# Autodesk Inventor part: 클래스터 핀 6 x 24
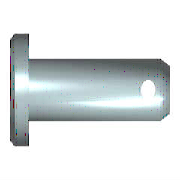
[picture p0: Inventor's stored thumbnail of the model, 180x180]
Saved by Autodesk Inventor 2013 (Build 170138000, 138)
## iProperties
IsCustomPart: 1
Created: 2012-02
Part Number: 클래스터 핀 6 x 24
Material: 강철
Description: 머리가 있는 클레비스 핀
Document SubType Name: Modeling
Standard: ISO 2341
Designer: mduedu
Standard Revision: Second edition 1986-11-01
Standards Organization: ISO
Language: ko-KR
Size Designation: B - 6 x 24
Categories: <MemberInstance><Categories><Category DisplayName="조임쇠" InternalName="e4da775c-781d-43d5-af7c-5136215cf5a6" Mnemonic="FSTN"><Category DisplayName="핀" InternalNa
Density: 7.85 g/cm^3
Author: mduedu
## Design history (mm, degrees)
sketch "스케치1"
  geometry: L1 (-2, 0)-(-2, 5); L2 (-2, 5)-(0, 5); L3 (0, 5)-(0, 3); L4 (0, 3)-(24, 3); L5 (24, 3)-(24, 0); L6 (-2, 0)-(24, 0); L7 (-4, 0)-(17, 0) reference; L8 (0, -0.98)-(0, 3.08) reference; C1 r 0.8 at (20.8, 0)
  constraints: 12 end point, 3 parallel, 2 collinear, 2 perpendicular, 1 centre point, 1 point on line, 1 vertical
  dimensions: "d0" = 6 diameter of L4 L6 (= NND); "d1" = 10 diameter of L2 L6 (= KOD); "d2" = 2 distance of L1.end L2.end (= KOH); "d3" = 24 distance of L3.end L4.end (= NLG); "d5" = 3.2 distance from line of L5 C1.centre (= DIST); "d6" = 1.6 diameter of C1 (= BOR)
revolve "본체" stored, may be unused: angle "d4" = 90 deg
extrude "구멍" cut sketch "스케치1" stored distance "d7" = 6 (= NND); taper "d8" = 0 deg
workaxis "Work Axis1"
workplane "Work Plane1"
node "작업축3"
node "작업 평면4"
body "Solid1"
chamfer "모따기1" distance "d9" = 1 (= PHH2); stored, may be unused: angle "d10" = 45 deg (= FAWI2), second distance "d16" = 1 (= PHH2)
chamfer "모따기2" distance "d11" = 2 (= PHH1); stored, may be unused: angle "d12" = 30 deg (= FAWI1), second distance "d17" = 2 (= PHH1)
other parameters: "PHH1" = 2 [user parameter; used in 2 equation terms], "PHH2" = 1 [user parameter; used in 2 equation terms], "KOD" = 10 [user parameter; used in 1 equation term], "KOH" = 2 [user parameter; used in 1 equation term], "NND" = 6 [user parameter; used in 2 equation terms], "FAWI1" = 30 deg [user parameter; used in 1 equation term], "FAWI2" = 45 deg [user parameter; used in 1 equation term], "DIST" = 3.2 [user parameter; used in 1 equation term], "BOR" = 1.6 [user parameter; used in 1 equation term], "NLG" = 24 [user parameter; used in 1 equation term], "d13" = 0, "d14" = 0, "d27" = 0, "d28" = 0, "d29" = 0, "d30" = 0, "d31" = 0
